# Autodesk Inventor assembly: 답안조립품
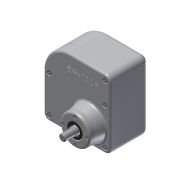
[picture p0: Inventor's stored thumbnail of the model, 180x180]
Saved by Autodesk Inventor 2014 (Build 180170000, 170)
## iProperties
Created: 2015-11
Part Number: 답안조립품
Document SubType Name: Assembly
Designer: SURY
Author: SURY
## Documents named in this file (13)
- C:\Users\SURY\Desktop\Inventor2급-황민연\2급\답안파일\답안조립품.iam
- C:\Users\SURY\Desktop\Inventor2급-황민연\2급\답안파일\1-본체.ipt
- C:\Users\SURY\Desktop\Inventor2급-황민연\2급\공용부품_20151104_2\앞커버.ipt
- C:\Users\SURY\Desktop\Inventor2급-황민연\2급\공용부품_20151104_2\베어링 6002.ipt
- C:\Users\SURY\Desktop\Inventor2급-황민연\2급\공용부품_20151104_2\축 커버.ipt
- C:\Users\SURY\Desktop\Inventor2급-황민연\2급\공용부품_20151104_2\베어링 6001.ipt
- C:\Users\SURY\Desktop\Inventor2급-황민연\2급\공용부품_20151104_2\로드 축.ipt
- C:\Users\SURY\Desktop\Inventor2급-황민연\2급\공용부품_20151104_2\편심 축.ipt
- C:\Users\SURY\Desktop\Inventor2급-황민연\2급\공용부품_20151104_2\로드.ipt
- C:\Users\SURY\Desktop\Inventor2급-황민연\2급\공용부품_20151104_2\오일실 15 x 25.ipt
- C:\Users\SURY\Desktop\Inventor2급-황민연\2급\공용부품_20151104_2\오일실 12 x 22.ipt
- C:\Users\SURY\Desktop\Inventor2급-황민연\2급\공용부품_20151104_2\M4 x 0.7.ipt
- C:\Users\SURY\Desktop\Inventor2급-황민연\2급\공용부품_20151104_2\M3 x 0.5.ipt
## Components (10 placed, 3 different names)
1. 1-본체:1
2. M4 x 0.7:1
3. M4 x 0.7:2
4. M4 x 0.7:3
5. M4 x 0.7:4
6. M4 x 0.7:5
7. M3 x 0.5:1
8. M3 x 0.5:2
9. M3 x 0.5:3
10. M3 x 0.5:4
